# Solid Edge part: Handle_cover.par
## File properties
Author: jmrobins
Template: Normal.par
Last saved by: rkriggs
Revision: 48
Application: Solid Edge
Density: 0.00000122 kg/mm^3
Accuracy: 0.99
Material: Nylon, general purpose
Face Style: Green
Fill Style: ANSI34(Plastic)
Virtual Style: White (Dull)
Coef. of Thermal Exp: 2.9e-05
Thermal Conductivity: 2.1
Specific Heat: 1675.0
Modulus of Elasticity: 1378951400.0
Poission's Ratio: 0.4
Yield Stress: 37921163.5
Ultimate Stress: 0.0
Elongation: 0.0
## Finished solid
Body 1: solid body, 20 faces, 38 edges, 20 vertices.
  Faces by surface: cylinder 9, plane 7, sphere 4
  Edges by curve: line 20, circle 18
Bounding box of the edges (mm; curved faces can reach further): 70.000 x 24.000 x 14.000, from (0, -12, -7) to (70, 12, 7).
Cylindrical faces by radius (mm): R5 x9
Spherical faces by radius (mm): R5 x4
Planar faces by outward normal: +x 1, +y 1, +z 1, -x 2, -y 1, -z 1
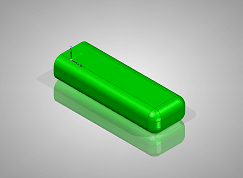
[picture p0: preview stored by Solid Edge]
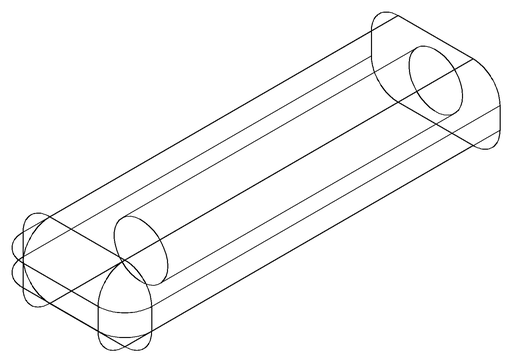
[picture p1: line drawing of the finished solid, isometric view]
